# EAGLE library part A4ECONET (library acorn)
Acorn A4 computer Econet bay interface
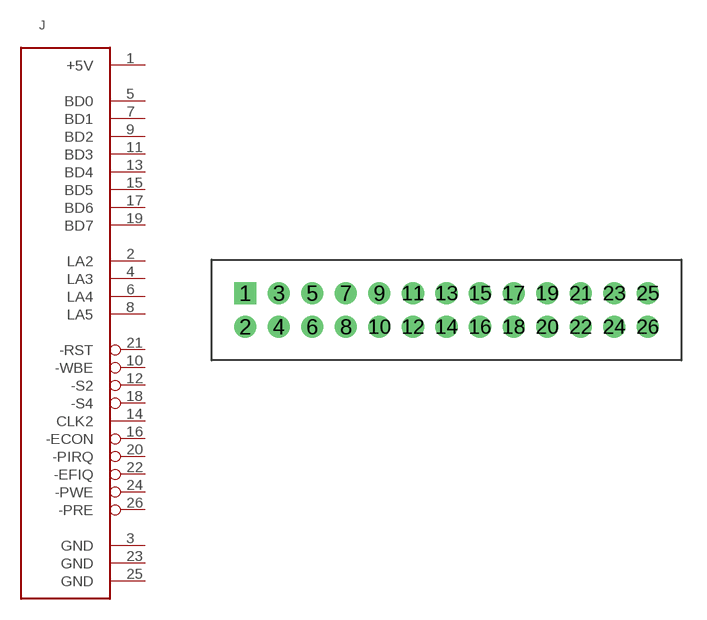
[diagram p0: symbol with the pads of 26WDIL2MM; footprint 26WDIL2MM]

Designator prefix J

## A4ECONET  [26WDIL2MM]
1  +5V  pwr
2  LA2  out
3  GND  pwr
4  LA3  out
5  BD0
6  LA4  out
7  BD1
8  LA5  out
9  BD2
10  -WBE  out
11  BD3
12  -S2  out
13  BD4
14  CLK2  out
15  BD5
16  -ECON  out
17  BD6
18  -S4  out
19  BD7
20  -PIRQ  oc
21  -RST  out
22  -EFIQ  oc
23  GND  pwr
24  -PWE  out
25  GND  pwr
26  -PRE  out

## Footprint 26WDIL2MM (pad centres in mm)
Acorn A4 Econet slot
drill 0.813 square: 1 -16,6
drill 0.813 round: 2 -16,4; 3 -14,6; 4 -14,4; 5 -12,6; 6 -12,4; 7 -10,6; 8 -10,4; 9 -8,6; 10 -8,4; 11 -6,6; 12 -6,4; 13 -4,6; 14 -4,4; 15 -2,6; 16 -2,4; 17 0,6; 18 0,4; 19 2,6; 20 2,4; 21 4,6; 22 4,4; 23 6,6; 24 6,4; 25 8,6; 26 8,4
